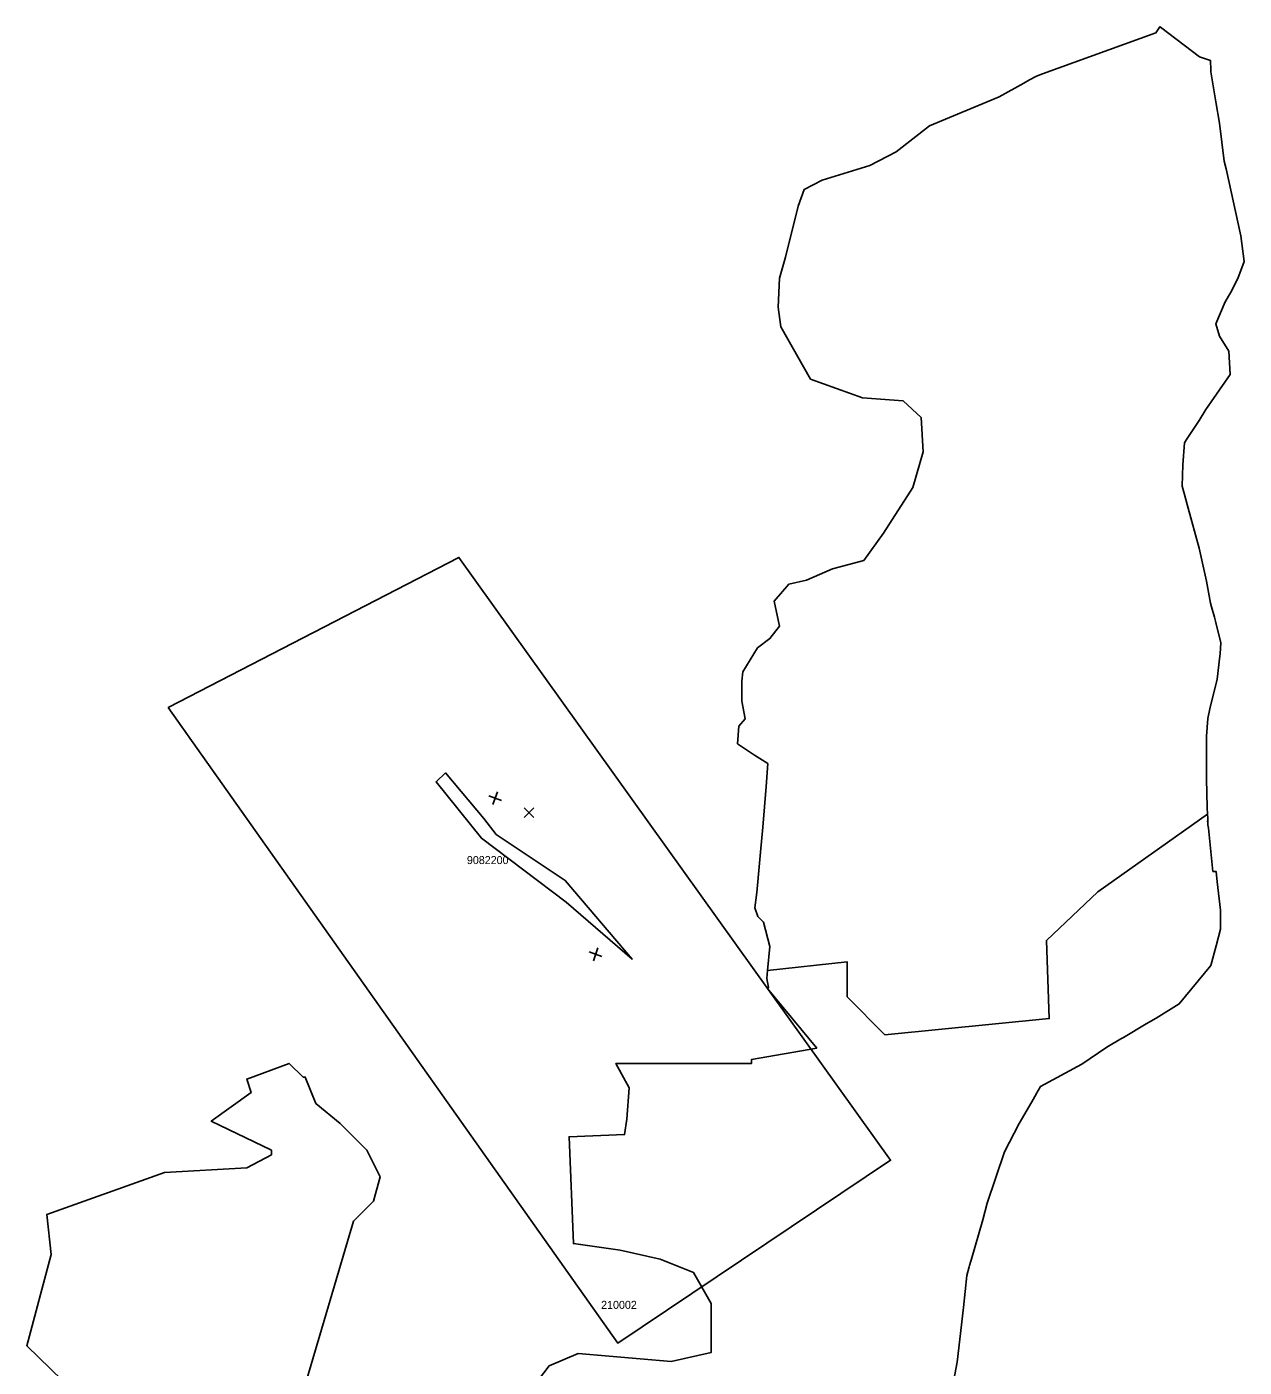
# Model space of a CAD drawing. Extents: x -556199 to -540209, y -1046851 to -1035695.
# Drawn here: x -541730 to -540209, y -1040187 to -1038513 of the extents above; entities that cross this region are included whole.
import ezdxf

# ---------------------------------------------------------------- set-up
doc = ezdxf.new("R2010")
doc.units = 0
for name, color, linetype in [('ft_08_KOMS_rr_trasa_l_RRT_STAV', 7, 'Continuous'), ('Vrstva 24', 7, 'Continuous'), ('Vrstva 43', 7, 'Continuous'), ('Vrstva 46', 7, 'Continuous')]:
    doc.layers.add(name, color=color, linetype=linetype)

msp = doc.modelspace()

# ---------------------------------------------------------------- linework, layer by layer
at = {"layer": 'ft_08_KOMS_rr_trasa_l_RRT_STAV'}
for p, q in [((-541153, -1039473.3), (-541137, -1039479)), ((-541142.2, -1039468.2), (-541147.9, -1039484.2)), ((-541108.8, -1039488.1), (-541096.8, -1039500.1)), ((-541096.8, -1039488.1), (-541108.8, -1039500.1)), ((-541016.6, -1039663.2), (-541022.3, -1039679.2)), ((-541027.4, -1039668.3), (-541011.5, -1039674.1))]:
    msp.add_line(p, q, dxfattribs=at)
at = {"layer": 'Vrstva 24'}
for points in [[(-540254.9, -1039496), (-540255.2, -1039487.7), (-540256.3, -1039452), (-540256.4, -1039398.8), (-540254.6, -1039376.5), (-540252.2, -1039364.5), (-540242.8, -1039327.7), (-540239.5, -1039298.8), (-540239.3, -1039295.7), (-540238.5, -1039282), (-540245.1, -1039255), (-540246.3, -1039250.1), (-540249.9, -1039237), (-540251.2, -1039232.6), (-540256.2, -1039205.1), (-540265.4, -1039163.9), (-540274.4, -1039130.6), (-540280.3, -1039109.2), (-540283.5, -1039097), (-540286.5, -1039086.2), (-540285.6, -1039059.8), (-540283.5, -1039032.2), (-540281, -1039028.2), (-540265.5, -1039004.5), (-540257.2, -1038990.8), (-540226.8, -1038947.1), (-540228.4, -1038917.7), (-540239.8, -1038899.1), (-540244.7, -1038883.7), (-540232.7, -1038856), (-540226.4, -1038844.9), (-540216.9, -1038827), (-540209.1, -1038805.6), (-540213.5, -1038773.7), (-540231.8, -1038690.1), (-540234.2, -1038680.4), (-540240.1, -1038632.8), (-540244.7, -1038606.2), (-540250.7, -1038568.9), (-540250.6, -1038566.3), (-540251.4, -1038554.6), (-540264.8, -1038549.9), (-540313.8, -1038513.1), (-540314.5, -1038512.6), (-540319.5, -1038520.2), (-540461, -1038571.2), (-540468.4, -1038574.3), (-540477.3, -1038578.8), (-540484.5, -1038583), (-540515.3, -1038599.9), (-540602.5, -1038636.4), (-540644.1, -1038668.9), (-540676.7, -1038685.8), (-540736.5, -1038704), (-540758.7, -1038715.8), (-540766.5, -1038736.6), (-540782.1, -1038800.4), (-540789.9, -1038826.4), (-540791.2, -1038862.8), (-540788, -1038887.3), (-540750.8, -1038952.6), (-540685.8, -1038976.1), (-540635, -1038980), (-540612.9, -1039000.8), (-540610.3, -1039043.7), (-540623.3, -1039088), (-540659.7, -1039145.3), (-540684.5, -1039179.1), (-540723.5, -1039189.5), (-540756.1, -1039203.8), (-540778.2, -1039209), (-540796.4, -1039229.9), (-540789.9, -1039261.1), (-540801.6, -1039276.7), (-540817.2, -1039288.4), (-540835.4, -1039318.4), (-540836.8, -1039330.1), (-540836.8, -1039354.8), (-540832.8, -1039376.9), (-540840.7, -1039386), (-540842, -1039408.2), (-540821.1, -1039422.5), (-540804.2, -1039432.9), (-540806.5, -1039461.7), (-540810.7, -1039512.3), (-540813.3, -1039543.5), (-540818.2, -1039593.8), (-540820.6, -1039613.3), (-540816.7, -1039624.1), (-540809.9, -1039630.9), (-540801.6, -1039661.6), (-540804.7, -1039691.3), (-540705, -1039680.8), (-540705, -1039724.5), (-540657.9, -1039771.6), (-540452.7, -1039751.4), (-540456, -1039653.9), (-540392.1, -1039593.3), (-540254.9, -1039496)], [(-540254.9, -1039496), (-540392.1, -1039593.3), (-540456, -1039653.9), (-540452.7, -1039751.4), (-540657.9, -1039771.6), (-540705, -1039724.5), (-540705, -1039680.8), (-540804.7, -1039691.3), (-540805.5, -1039701.6), (-540803.3, -1039712.8), (-540805.2, -1039713.3), (-540805.3, -1039713.3), (-540743.2, -1039788.3), (-540824.6, -1039802.5), (-540824.6, -1039807.6), (-540994, -1039807.6), (-540977.7, -1039838.1), (-540980.4, -1039877), (-540983.2, -1039896.4), (-541052.6, -1039899.2), (-541047.1, -1040032.5), (-540988.8, -1040040.8), (-540938.8, -1040051.9), (-540897.1, -1040068.6), (-540874.9, -1040107.5), (-540874.9, -1040168.5), (-540924.9, -1040179.7), (-541041.1, -1040169.8), (-541077.6, -1040185.2), (-541138.7, -1040265.7)], [(-540581.1, -1040251.2), (-540567.6, -1040180.7), (-540559.8, -1040112.4), (-540555.8, -1040072.3), (-540552.8, -1040061.7), (-540552.2, -1040059.8), (-540550.7, -1040054.7), (-540550.3, -1040053.3), (-540535.8, -1040002.7), (-540530.4, -1039982.1), (-540508.7, -1039918.1), (-540490.1, -1039882.7), (-540471.7, -1039850.5), (-540471.4, -1039850), (-540469.9, -1039847.4), (-540469.3, -1039846.4), (-540463.5, -1039836.2), (-540411.8, -1039808.5), (-540380.6, -1039787.4), (-540363.1, -1039776.9), (-540360, -1039775.1), (-540331.5, -1039758.2), (-540319.1, -1039751.1), (-540290.2, -1039733.2), (-540250.8, -1039685.1), (-540244.3, -1039660.5), (-540238.8, -1039639.6), (-540238.7, -1039616.1), (-540242.8, -1039580.5), (-540244.1, -1039567.8), (-540248.1, -1039567.6), (-540253.8, -1039513.8), (-540253.9, -1039513.6), (-540254.6, -1039509.6), (-540254.6, -1039506.2), (-540254.8, -1039505), (-540254.9, -1039505.1), (-540254.7, -1039503.9), (-540254.7, -1039501.1), (-540254.9, -1039496)], [(-541380.3, -1040201.9), (-541322, -1040004.7), (-541297, -1039979.7), (-541288.7, -1039949.2), (-541305.3, -1039915.9), (-541338.6, -1039882.5), (-541369.2, -1039857.5), (-541382.2, -1039824.5), (-541384.8, -1039824.5), (-541402.5, -1039807.6), (-541455.3, -1039827), (-541449.7, -1039843.7), (-541499.7, -1039879.8), (-541424.6, -1039916), (-541424.6, -1039921.6), (-541455.3, -1039938.1), (-541558, -1039943.6), (-541705.2, -1039996.4), (-541699.6, -1040046.4), (-541730.2, -1040160.2), (-541641.3, -1040246.3)]]:
    msp.add_lwpolyline(points, dxfattribs=at)
at = {"layer": 'Vrstva 43'}
msp.add_lwpolyline([(-541159.3, -1039501.5), (-541207.2, -1039444.6), (-541218.8, -1039455.6), (-541162.1, -1039526.2), (-541056.2, -1039606.1), (-540974, -1039677.3), (-541057.4, -1039578.9), (-541143.6, -1039521.6)], close=True, dxfattribs=at)
at = {"layer": 'Vrstva 46'}
msp.add_lwpolyline([(-541553.6, -1039362.8), (-540991.8, -1040156.9), (-540650.9, -1039928.4), (-541190.3, -1039175.5)], close=True, dxfattribs=at)

# ---------------------------------------------------------------- texts
at = {"layer": 'Vrstva 43'}
msp.add_text('9082200', height=10, dxfattribs=at).set_placement((-541180.3, -1039558.5))
at = {"layer": 'Vrstva 46'}
msp.add_text('210002', height=10, dxfattribs=at).set_placement((-541012.6, -1040114.1))

doc.saveas('drawing.dxf')
